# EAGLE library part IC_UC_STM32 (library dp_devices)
STM32F102C6
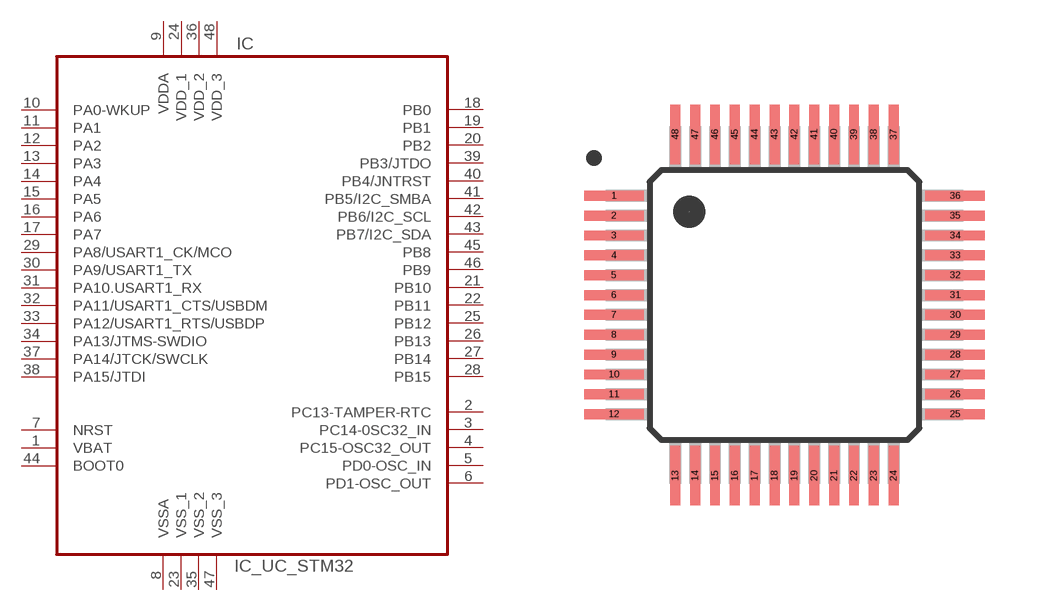
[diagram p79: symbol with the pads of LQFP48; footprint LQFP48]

Designator prefix IC

## IC_UC_STM32  [LQFP48]
1  VBAT
2  PC13-TAMPER-RTC
3  PC14-0SC32_IN
4  PC15-OSC32_OUT
5  PD0-OSC_IN
6  PD1-OSC_OUT
7  NRST
8  VSSA  sup
9  VDDA  pwr
10  PA0-WKUP
11  PA1
12  PA2
13  PA3
14  PA4
15  PA5
16  PA6
17  PA7
18  PB0
19  PB1
20  PB2
21  PB10
22  PB11
23  VSS_1  sup
24  VDD_1  pwr
25  PB12
26  PB13
27  PB14
28  PB15
29  PA8/USART1_CK/MCO
30  PA9/USART1_TX
31  PA10.USART1_RX
32  PA11/USART1_CTS/USBDM
33  PA12/USART1_RTS/USBDP
34  PA13/JTMS-SWDIO
35  VSS_2  sup
36  VDD_2  pwr
37  PA14/JTCK/SWCLK
38  PA15/JTDI
39  PB3/JTDO
40  PB4/JNTRST
41  PB5/I2C_SMBA
42  PB6/I2C_SCL
43  PB7/I2C_SDA
44  BOOT0
45  PB8
46  PB9
47  VSS_3  sup
48  VDD_3  pwr

## Footprint LQFP48 (pad centres in mm)
smd 1.5 x 0.25: 1 -4.3,2.75; 2 -4.3,2.25; 3 -4.3,1.75; 4 -4.3,1.25; 5 -4.3,0.75; 6 -4.3,0.25; 7 -4.3,-0.25; 8 -4.3,-0.75; 9 -4.3,-1.25; 10 -4.3,-1.75; 11 -4.3,-2.25; 12 -4.3,-2.75; 25 4.3,-2.75; 26 4.3,-2.25; 27 4.3,-1.75; 28 4.3,-1.25; 29 4.3,-0.75; 30 4.3,-0.25; 31 4.3,0.25; 32 4.3,0.75; 33 4.3,1.25; 34 4.3,1.75; 35 4.3,2.25; 36 4.3,2.75
smd 0.25 x 1.5: 13 -2.75,-4.3; 14 -2.25,-4.3; 15 -1.75,-4.3; 16 -1.25,-4.3; 17 -0.75,-4.3; 18 -0.25,-4.3; 19 0.25,-4.3; 20 0.75,-4.3; 21 1.25,-4.3; 22 1.75,-4.3; 23 2.25,-4.3; 24 2.75,-4.3; 37 2.75,4.3; 38 2.25,4.3; 39 1.75,4.3; 40 1.25,4.3; 41 0.75,4.3; 42 0.25,4.3; 43 -0.25,4.3; 44 -0.75,4.3; 45 -1.25,4.3; 46 -1.75,4.3; 47 -2.25,4.3; 48 -2.75,4.3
